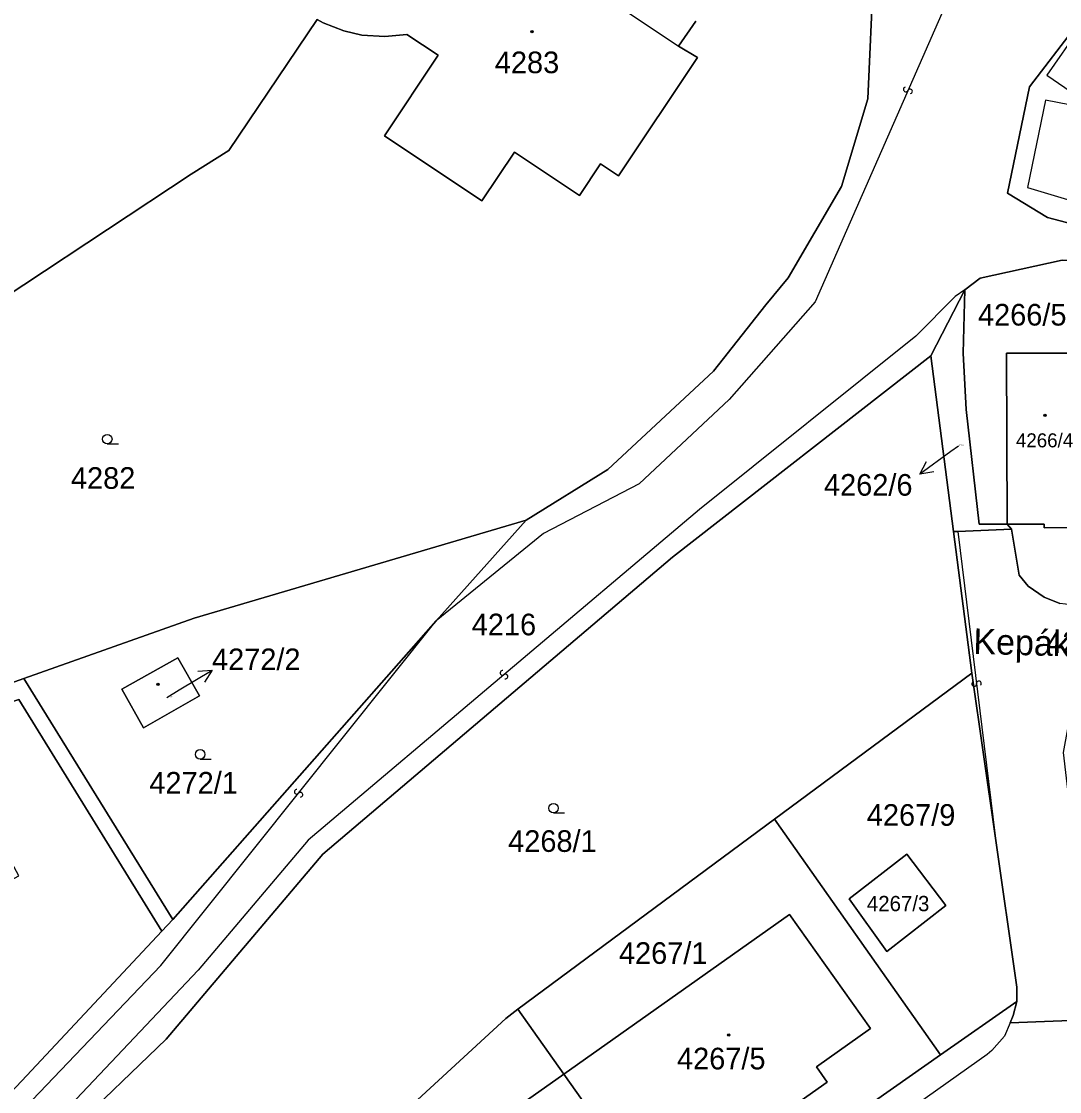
# Model space of a CAD drawing. Extents: x -598233 to -596890, y -1157848 to -1156431.
# Drawn here: x -598132 to -598050.5, y -1156881.8 to -1156797.7 of the extents above; entities that cross this region are included whole.
import ezdxf

# ---------------------------------------------------------------- set-up
doc = ezdxf.new("R2010")
doc.units = 0
for name, color, linetype in [('Level 1', 7, 'Continuous'), ('Level 11', 7, 'Continuous'), ('Level 13', 7, 'Continuous'), ('Level 3', 7, 'Continuous'), ('Level 4', 7, 'Continuous'), ('Level 5', 7, 'Continuous'), ('Level 57', 7, 'Continuous'), ('Level 60', 7, 'Continuous'), ('Vrstva 60', 7, 'Continuous')]:
    doc.layers.add(name, color=color, linetype=linetype)

msp = doc.modelspace()

# ---------------------------------------------------------------- linework, layer by layer
at = {"layer": 'Level 1'}
for points in [[(-598092.4, -1156836.89), (-598085.97, -1156832.9), (-598077.69, -1156825.18), (-598073.58, -1156819.96), (-598071.82, -1156817.85), (-598067.63, -1156810.67), (-598065.55, -1156803.78), (-598065.12, -1156793.87), (-598064.03, -1156782.95)], [(-598193.56, -1156855.54), (-598177.71, -1156844.1), (-598172.49, -1156840.81), (-598160.03, -1156833.51), (-598138.46, -1156822.74), (-598118.7, -1156809.71), (-598115.76, -1156807.85), (-598108.81, -1156797.54)], [(-598108.81, -1156797.54), (-598108.35, -1156797.82), (-598106.72, -1156798.44), (-598105.3, -1156798.77), (-598103.49, -1156798.88), (-598101.76, -1156798.74), (-598099.31, -1156800.34), (-598103.53, -1156806.7), (-598095.87, -1156811.8), (-598093.31, -1156807.97), (-598088.21, -1156811.39), (-598086.56, -1156808.89), (-598085.15, -1156809.84), (-598078.94, -1156800.54), (-598080.42, -1156799.65)], [(-598080.42, -1156799.65), (-598079.08, -1156797.67)], [(-598049.17, -1156798.01), (-598052.86, -1156802.85), (-598054.6, -1156811.2), (-598051.46, -1156813.11), (-598048.57, -1156813.86), (-598042.42, -1156814.92)], [(-598048.28, -1156816.58), (-598050.29, -1156816.45), (-598056.74, -1156817.87), (-598057.95, -1156818.8)], [(-598057.95, -1156818.8), (-598060.62, -1156823.99)], [(-598054.61, -1156837.21), (-598056.81, -1156837.22), (-598057.83, -1156828.19), (-598058.06, -1156823.77), (-598057.95, -1156818.8)], [(-598060.62, -1156823.99), (-598080.91, -1156839.8), (-598108.36, -1156863.13), (-598120.66, -1156877.67), (-598128.28, -1156885.01)], [(-598058.83, -1156837.79), (-598060.62, -1156823.99)], [(-598048.28, -1156823.76), (-598054.66, -1156823.76), (-598054.61, -1156837.21)], [(-598092.4, -1156836.89), (-598118.46, -1156844.59), (-598131.84, -1156849.33)], [(-598099.46, -1156844.8), (-598092.4, -1156836.89)], [(-598058.48, -1156837.78), (-598058.83, -1156837.79)], [(-598057.38, -1156848.91), (-598058.83, -1156837.79)], [(-598054.27, -1156837.59), (-598058.48, -1156837.78)], [(-598048.28, -1156837.48), (-598051.71, -1156837.5), (-598051.71, -1156837.2), (-598054.61, -1156837.21)], [(-598054.27, -1156837.59), (-598054.61, -1156837.21)], [(-598045.6, -1156876.06), (-598046.55, -1156875.02), (-598047.64, -1156873.15), (-598048.33, -1156871.04), (-598050.2, -1156855.14), (-598049.84, -1156853.3), (-598048.69, -1156851.57), (-598047.07, -1156850.51), (-598046.08, -1156850.15), (-598015.82, -1156850.28), (-598015.89, -1156843.82), (-598048.25, -1156843.71), (-598050.49, -1156843.44), (-598051.7, -1156842.94), (-598052.96, -1156842.07), (-598053.68, -1156841.22), (-598054.27, -1156837.59)], [(-598120.16, -1156868.28), (-598099.46, -1156844.8)], [(-598124.15, -1156850.18), (-598119.75, -1156847.72), (-598118.05, -1156850.7), (-598122.45, -1156853.22), (-598124.15, -1156850.18)], [(-598057.38, -1156848.91), (-598072.89, -1156860.4)], [(-598057.38, -1156848.91), (-598055.56, -1156861.7)], [(-598131.84, -1156849.33), (-598138.53, -1156851.73), (-598150.65, -1156850.55), (-598155.84, -1156850.09), (-598163.69, -1156850.8), (-598171.6, -1156851.6), (-598186.35, -1156859.13), (-598199.39, -1156870.12)], [(-598120.16, -1156868.28), (-598131.84, -1156849.33)], [(-598121.01, -1156869.19), (-598132.23, -1156850.98), (-598138.4, -1156852.95)], [(-598093.05, -1156875.33), (-598072.89, -1156860.4)], [(-598072.89, -1156860.4), (-598059.85, -1156878.92)], [(-598055.56, -1156861.7), (-598053.86, -1156873.59), (-598053.86, -1156874.72)], [(-598062.5, -1156863.14), (-598059.44, -1156867.17), (-598064.07, -1156870.8), (-598067.03, -1156866.66), (-598062.5, -1156863.14)], [(-598083.08, -1156889.4), (-598078.92, -1156886.45), (-598078.08, -1156887.64), (-598068.75, -1156881.06), (-598069.6, -1156879.85), (-598065.36, -1156876.85), (-598071.72, -1156867.87), (-598089.44, -1156880.42)], [(-598120.16, -1156868.28), (-598121.01, -1156869.19)], [(-598121.01, -1156869.19), (-598132.02, -1156880.94), (-598145.06, -1156894.74)], [(-598059.85, -1156878.92), (-598053.86, -1156874.72)], [(-598054.38, -1156876.39), (-598054.14, -1156875.81), (-598053.86, -1156874.72)], [(-598116.46, -1156896.74), (-598094, -1156876.04), (-598093.05, -1156875.33)], [(-598093.05, -1156875.33), (-598089.44, -1156880.42)], [(-598045.6, -1156876.06), (-598054.38, -1156876.39)], [(-598080.33, -1156893.28), (-598059.85, -1156878.92)], [(-598106.88, -1156893.32), (-598107.16, -1156892.94), (-598089.44, -1156880.42)], [(-598089.44, -1156880.42), (-598083.08, -1156889.4)]]:
    msp.add_lwpolyline(points, dxfattribs=at)
at = {"layer": 'Level 13'}
for centre, start, end in [((-598062.578, -1156803.045), 103.47467, 336.06467), ((-598062.242, -1156803.196), 283.68912, 155.78712), ((-598094.258, -1156848.899), 77.35201, 309.94201), ((-598094.022, -1156849.182), 257.56647, 129.66446), ((-598057.203, -1156849.762), 134.11814, 6.70814), ((-598056.837, -1156849.719), 314.3326, 186.43059), ((-598110.413, -1156858.234), 88.76713, 320.86513), ((-598110.127, -1156858.465), 268.55268, 141.14268)]:
    msp.add_arc(centre, 0.184, start, end, dxfattribs=at)
at = {"layer": 'Level 3'}
for points in [[(-598055.12, -1156786.5), (-598069.7, -1156819.74), (-598076.45, -1156827.42), (-598083.53, -1156834.04), (-598091.04, -1156837.93), (-598099.46, -1156844.8)], [(-598093.5, -1156790.91), (-598080.42, -1156799.65)], [(-598048.9, -1156798.2), (-598051.49, -1156801.93), (-598049.17, -1156803.51), (-598049.73, -1156804.25), (-598051.61, -1156803.9), (-598053.01, -1156810.74), (-598044.99, -1156813.17), (-598039.26, -1156805.12)], [(-598057.95, -1156818.8), (-598058.69, -1156819.33), (-598061.79, -1156822.43), (-598078.77, -1156836.05), (-598109.52, -1156862.03), (-598118.15, -1156872.26), (-598141.43, -1156896.84), (-598150.37, -1156905.66), (-598157.25, -1156912.11), (-598177.03, -1156929.81)], [(-598058.48, -1156837.78), (-598055.56, -1156861.7)], [(-598179.09, -1156927.87), (-598158.76, -1156910), (-598144.1, -1156895.96), (-598121.09, -1156871.89), (-598099.46, -1156844.8)], [(-598054.38, -1156876.39), (-598054.82, -1156877.44), (-598055.82, -1156878.56), (-598056.2, -1156878.89), (-598069.81, -1156888.54), (-598082.39, -1156897.45), (-598094.37, -1156905.95), (-598097.13, -1156908.37)]]:
    msp.add_lwpolyline(points, dxfattribs=at)
at = {"layer": 'Level 5'}
for p, q in [((-598125.3, -1156830.9), (-598124.425, -1156830.9)), ((-598118, -1156855.67), (-598117.125, -1156855.67)), ((-598090.25, -1156859.9), (-598089.375, -1156859.9))]:
    msp.add_line(p, q, dxfattribs=at)
for centre, radius in [((-598091.94, -1156798.5), 0.09), ((-598091.94, -1156798.5), 0.0521), ((-598051.65, -1156828.66), 0.09), ((-598051.65, -1156828.66), 0.0521), ((-598125.3, -1156830.525), 0.375), ((-598121.32, -1156849.8), 0.09), ((-598121.32, -1156849.8), 0.0521), ((-598118, -1156855.295), 0.375), ((-598090.25, -1156859.525), 0.375), ((-598076.49, -1156877.36), 0.09), ((-598076.49, -1156877.36), 0.0521)]:
    msp.add_circle(centre, radius, dxfattribs=at)
at = {"layer": 'Level 57'}
for p, q in [((-598058.44, -1156831.07), (-598059.042, -1156831.507)), ((-598059.042, -1156831.507), (-598061.47, -1156833.27)), ((-598119.637, -1156850.232), (-598117.07, -1156848.68)), ((-598120.61, -1156850.82), (-598119.637, -1156850.232))]:
    msp.add_line(p, q, dxfattribs=at)
for points in [[(-598060.367, -1156833.087), (-598061.47, -1156833.27), (-598060.954, -1156832.277)], [(-598118.184, -1156848.769), (-598117.07, -1156848.68), (-598117.667, -1156849.625)]]:
    msp.add_lwpolyline(points, dxfattribs=at)
at = {"layer": 'Level 60'}
for points in [[(-598065.12, -1156793.87), (-598065.55, -1156803.78), (-598067.63, -1156810.67), (-598071.82, -1156817.85), (-598073.58, -1156819.96), (-598077.69, -1156825.18), (-598085.97, -1156832.9), (-598092.4, -1156836.89), (-598118.46, -1156844.59), (-598131.84, -1156849.33), (-598138.53, -1156851.73)], [(-598108.81, -1156797.54), (-598115.76, -1156807.85), (-598118.7, -1156809.71), (-598138.46, -1156822.74), (-598160.03, -1156833.51), (-598172.49, -1156840.81), (-598177.71, -1156844.1), (-598193.56, -1156855.54), (-598194.72, -1156851.49), (-598180.46, -1156837.75), (-598158.65, -1156818.85), (-598158.31, -1156818.54), (-598154.36, -1156815.18), (-598145.87, -1156807.79), (-598143.19, -1156804.8), (-598135.67, -1156796.45)], [(-598138.46, -1156822.74), (-598118.7, -1156809.71), (-598115.76, -1156807.85), (-598108.81, -1156797.54), (-598108.35, -1156797.82), (-598106.72, -1156798.44), (-598105.3, -1156798.77), (-598103.49, -1156798.88), (-598101.76, -1156798.74), (-598099.31, -1156800.34), (-598103.53, -1156806.7), (-598095.87, -1156811.8), (-598093.31, -1156807.97), (-598088.21, -1156811.39), (-598086.56, -1156808.89), (-598085.15, -1156809.84), (-598078.94, -1156800.54), (-598080.42, -1156799.65), (-598079.08, -1156797.67)], [(-598079.08, -1156797.67), (-598080.42, -1156799.65), (-598078.94, -1156800.54), (-598085.15, -1156809.84), (-598086.56, -1156808.89), (-598088.21, -1156811.39), (-598093.31, -1156807.97), (-598095.87, -1156811.8), (-598103.53, -1156806.7), (-598099.31, -1156800.34), (-598101.76, -1156798.74), (-598103.49, -1156798.88), (-598105.3, -1156798.77), (-598106.72, -1156798.44), (-598108.35, -1156797.82), (-598108.81, -1156797.54)], [(-598045.6, -1156876.06), (-598054.38, -1156876.39), (-598054.14, -1156875.81), (-598053.86, -1156874.72), (-598053.86, -1156873.59), (-598055.56, -1156861.7), (-598057.38, -1156848.91), (-598058.83, -1156837.79), (-598058.48, -1156837.78), (-598054.27, -1156837.59), (-598053.68, -1156841.22), (-598052.96, -1156842.07), (-598051.7, -1156842.94), (-598050.49, -1156843.44)], [(-598050.49, -1156843.44), (-598051.7, -1156842.94), (-598052.96, -1156842.07), (-598053.68, -1156841.22), (-598054.27, -1156837.59), (-598054.61, -1156837.21), (-598051.71, -1156837.2), (-598051.71, -1156837.5), (-598048.28, -1156837.48)], [(-598080.33, -1156893.28), (-598059.85, -1156878.92), (-598053.86, -1156874.72), (-598054.14, -1156875.81), (-598054.38, -1156876.39), (-598045.6, -1156876.06), (-598018.25, -1156880.49), (-598016.53, -1156880.18), (-598015.01, -1156879.34), (-598013.25, -1156877.47), (-598013.76, -1156881.08), (-598016.24, -1156898.9)]]:
    msp.add_lwpolyline(points, dxfattribs=at)
for points in [[(-598054.6, -1156811.2), (-598052.86, -1156802.85), (-598049.17, -1156798.01), (-598048.9, -1156798.2), (-598039.26, -1156805.12), (-598036.85, -1156806.85), (-598042.42, -1156814.92), (-598048.57, -1156813.86), (-598051.46, -1156813.11)], [(-598056.74, -1156817.87), (-598050.29, -1156816.45), (-598048.28, -1156816.58), (-598048.28, -1156823.76), (-598054.66, -1156823.76), (-598054.61, -1156837.21), (-598056.81, -1156837.22), (-598057.83, -1156828.19), (-598058.06, -1156823.77), (-598057.95, -1156818.8)], [(-598054.61, -1156837.21), (-598054.27, -1156837.59), (-598058.48, -1156837.78), (-598058.83, -1156837.79), (-598060.62, -1156823.99), (-598057.95, -1156818.8), (-598058.06, -1156823.77), (-598057.83, -1156828.19), (-598056.81, -1156837.22)], [(-598080.91, -1156839.8), (-598060.62, -1156823.99), (-598058.83, -1156837.79), (-598057.38, -1156848.91), (-598072.89, -1156860.4), (-598093.05, -1156875.33), (-598094, -1156876.04), (-598116.46, -1156896.74), (-598118.65, -1156898.76), (-598128.28, -1156885.01), (-598120.66, -1156877.67), (-598108.36, -1156863.13)], [(-598048.28, -1156826.11), (-598048.28, -1156837.48), (-598051.71, -1156837.5), (-598051.71, -1156837.2), (-598054.61, -1156837.21), (-598054.66, -1156823.76), (-598048.28, -1156823.76)], [(-598092.4, -1156836.89), (-598099.46, -1156844.8), (-598120.16, -1156868.28), (-598131.84, -1156849.33), (-598118.46, -1156844.59)], [(-598124.15, -1156850.18), (-598119.75, -1156847.72), (-598118.05, -1156850.7), (-598122.45, -1156853.22)], [(-598119.75, -1156847.72), (-598124.15, -1156850.18), (-598122.45, -1156853.22), (-598118.05, -1156850.7)], [(-598072.89, -1156860.4), (-598057.38, -1156848.91), (-598055.56, -1156861.7), (-598053.86, -1156873.59), (-598053.86, -1156874.72), (-598059.85, -1156878.92)], [(-598138.53, -1156851.73), (-598131.84, -1156849.33), (-598120.16, -1156868.28), (-598121.01, -1156869.19), (-598132.23, -1156850.98), (-598138.4, -1156852.95), (-598155.73, -1156851.28), (-598162.98, -1156851.97), (-598171.24, -1156852.74), (-598185.58, -1156860.05), (-598199.34, -1156871.82), (-598200.21, -1156870.99), (-598199.39, -1156870.12), (-598186.35, -1156859.13), (-598171.6, -1156851.6), (-598163.69, -1156850.8), (-598155.84, -1156850.09), (-598150.65, -1156850.55)], [(-598121.01, -1156869.19), (-598132.02, -1156880.94), (-598145.06, -1156894.74), (-598147.34, -1156892.04), (-598146.09, -1156891.01), (-598157.12, -1156878.33), (-598132.24, -1156864.85), (-598135.14, -1156859.49), (-598135.17, -1156853.14), (-598138.57, -1156853.16), (-598138.4, -1156852.95), (-598132.23, -1156850.98)], [(-598089.44, -1156880.42), (-598093.05, -1156875.33), (-598072.89, -1156860.4), (-598059.85, -1156878.92), (-598080.33, -1156893.28), (-598083.08, -1156889.4), (-598078.92, -1156886.45), (-598078.08, -1156887.64), (-598068.75, -1156881.06), (-598069.6, -1156879.85), (-598065.36, -1156876.85), (-598071.72, -1156867.87)], [(-598062.5, -1156863.14), (-598059.44, -1156867.17), (-598064.07, -1156870.8), (-598067.03, -1156866.66)], [(-598059.44, -1156867.17), (-598062.5, -1156863.14), (-598067.03, -1156866.66), (-598064.07, -1156870.8)], [(-598083.08, -1156889.4), (-598089.44, -1156880.42), (-598071.72, -1156867.87), (-598065.36, -1156876.85), (-598069.6, -1156879.85), (-598068.75, -1156881.06), (-598078.08, -1156887.64), (-598078.92, -1156886.45)], [(-598116.46, -1156896.74), (-598094, -1156876.04), (-598093.05, -1156875.33), (-598089.44, -1156880.42), (-598107.16, -1156892.94), (-598106.88, -1156893.32), (-598114.85, -1156899.01)], [(-598106.88, -1156893.32), (-598107.16, -1156892.94), (-598089.44, -1156880.42), (-598083.08, -1156889.4), (-598087.27, -1156892.36), (-598086.4, -1156893.6), (-598095.71, -1156900.16), (-598096.57, -1156898.93), (-598100.81, -1156901.93), (-598105.1, -1156895.85)]]:
    msp.add_lwpolyline(points, close=True, dxfattribs=at)
at = {"layer": 'Vrstva 60'}
for points in [[(-598046.79, -1156796.42), (-598055.12, -1156786.5), (-598059.85, -1156780.87), (-598062.32, -1156767.72), (-598060.26, -1156738.45), (-598061.8, -1156746.4), (-598064.1, -1156760.98), (-598063.83, -1156781.44), (-598064.03, -1156782.95), (-598065.12, -1156793.87), (-598065.55, -1156803.78), (-598067.63, -1156810.67), (-598071.82, -1156817.85), (-598073.58, -1156819.96), (-598077.69, -1156825.18), (-598085.97, -1156832.9), (-598092.4, -1156836.89), (-598099.46, -1156844.8), (-598120.16, -1156868.28), (-598121.01, -1156869.19), (-598132.02, -1156880.94), (-598145.06, -1156894.74)], [(-598048.57, -1156813.86), (-598051.46, -1156813.11), (-598054.6, -1156811.2), (-598052.86, -1156802.85), (-598049.17, -1156798.01)], [(-598128.28, -1156885.01), (-598120.66, -1156877.67), (-598108.36, -1156863.13), (-598080.91, -1156839.8), (-598060.62, -1156823.99), (-598057.95, -1156818.8), (-598056.74, -1156817.87), (-598050.29, -1156816.45)]]:
    msp.add_lwpolyline(points, dxfattribs=at)

# ---------------------------------------------------------------- texts
at = {"layer": 'Level 11'}
msp.add_text('Kepákova', height=2, rotation=358.48579, dxfattribs=at).set_placement((-598057.294, -1156847.396))
at = {"layer": 'Level 4'}
for s, height, p in [('4283', 1.7, (-598094.858, -1156801.77)), ('4266/5', 1.7, (-598056.91, -1156821.6)), ('4266/4', 1.1, (-598053.93, -1156831.17)), ('4262/6', 0.1, (-598058.44, -1156831.07)), ('4282', 1.7, (-598128.15, -1156834.43)), ('4216', 1.7, (-598096.67, -1156845.94)), ('4266/1', 1.7, (-598051.55, -1156847.34)), ('4272/2', 0.1, (-598120.61, -1156850.82)), ('4272/1', 1.7, (-598121.99, -1156858.38)), ('4267/9', 1.7, (-598065.64, -1156860.91)), ('4268/1', 1.7, (-598093.81, -1156862.96)), ('4267/3', 1.2, (-598065.636, -1156867.62)), ('4267/1', 1.7, (-598085.11, -1156871.76)), ('4267/5', 1.7, (-598080.55, -1156880.05))]:
    msp.add_text(s, height=height, dxfattribs=at).set_placement(p)
at = {"layer": 'Level 57'}
for s, p in [('4262/6', (-598069.005, -1156834.97)), ('4272/2', (-598117.07, -1156848.68))]:
    msp.add_text(s, height=1.7, dxfattribs=at).set_placement(p)

doc.saveas('drawing.dxf')
